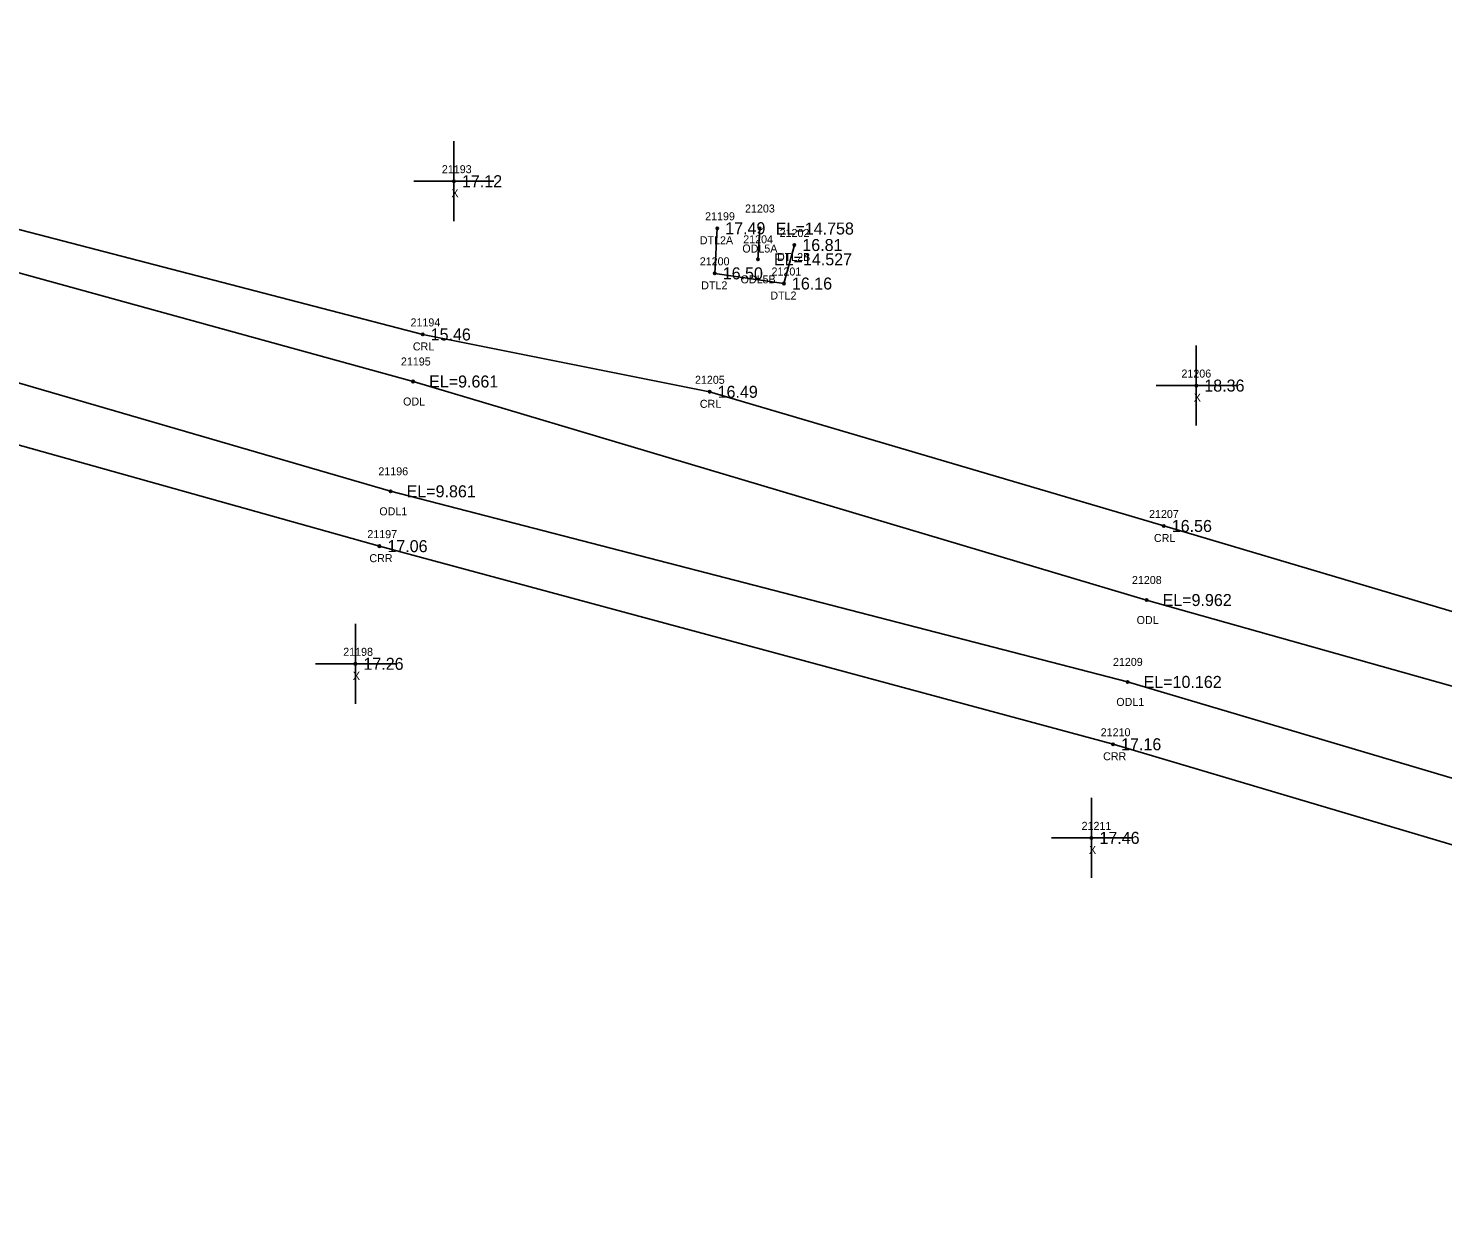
# Model space of a CAD drawing. Extents: x 2655177 to 2656219, y 761780 to 764748.
# Drawn here: x 2655865.5 to 2656042.3, y 763101.9 to 763251.6 of the extents above; entities that cross this region are included whole.
import ezdxf

# ---------------------------------------------------------------- set-up
doc = ezdxf.new("R2010")
doc.units = 0
for name, color, linetype in [('RD_EX_H2O', 7, 'Continuous'), ('RD_EX_H2O_txCode', 7, 'Continuous'), ('RD_EX_Misc', 7, 'Continuous'), ('RD_EX_Misc_txCode', 7, 'Continuous'), ('RD_EX_TX_H2O_ELEV', 7, 'Continuous'), ('RD_EX_TX_Misc_ELEV', 7, 'Continuous'), ('RD_SMD_Locator', 7, 'Continuous')]:
    doc.layers.add(name, color=color, linetype=linetype)

msp = doc.modelspace()

# ---------------------------------------------------------------- linework, layer by layer
at = {"layer": 'RD_EX_H2O'}
msp.add_line((2655956.93, 763226.61), (2655956.7, 763222.76), dxfattribs=at)
for points in [[(2655763.83, 763255.61), (2655817.49, 763238.63), (2655914.8, 763213.38), (2655950.66, 763206.21), (2656007.42, 763189.45), (2656109.25, 763159.23), (2656208.33, 763130.47)], [(2655756.39, 763249.8), (2655816.19, 763234.32), (2655913.6, 763207.5), (2656005.27, 763180.2), (2656107.53, 763151.42), (2656206.07, 763121.76)], [(2655730.43, 763238.59), (2655771.44, 763229.13), (2655791.17, 763220.85), (2655791.17, 763220.85), (2655810.24, 763214.7), (2655909.39, 763186.93), (2656001.09, 763162.18), (2656103.26, 763131.88), (2656200.94, 763101.91)], [(2655752.5, 763238.32), (2655812.56, 763222.36), (2655910.79, 763193.78), (2656002.9, 763169.97), (2656104.97, 763139.7), (2656202.94, 763109.66)], [(2655951.61, 763226.64), (2655951.3, 763221.01), (2655959.95, 763219.74), (2655961.25, 763224.55)]]:
    msp.add_lwpolyline(points, dxfattribs=at)
at = {"layer": 'RD_EX_Misc'}
for p, q in [((2655918.71, 763227.52), (2655918.71, 763237.52)), ((2655913.71, 763232.52), (2655923.71, 763232.52)), ((2656011.49, 763201.99), (2656011.49, 763211.99)), ((2656006.49, 763206.99), (2656016.49, 763206.99)), ((2655906.39, 763167.23), (2655906.39, 763177.23)), ((2655901.39, 763172.23), (2655911.39, 763172.23)), ((2655998.38, 763145.49), (2655998.38, 763155.49)), ((2655993.38, 763150.49), (2656003.38, 763150.49))]:
    msp.add_line(p, q, dxfattribs=at)
at = {"layer": 'RD_SMD_Locator'}
for centre in [(2655918.71, 763232.52), (2655951.61, 763226.64), (2655956.93, 763226.61), (2655961.25, 763224.55), (2655956.7, 763222.76), (2655951.3, 763221.01), (2655959.95, 763219.74), (2655914.8, 763213.38), (2655913.6, 763207.5), (2656011.49, 763206.99), (2655950.66, 763206.21), (2655910.79, 763193.78), (2656007.42, 763189.45), (2655909.39, 763186.93), (2656005.27, 763180.2), (2655906.39, 763172.23), (2656002.9, 763169.97), (2656001.09, 763162.18), (2655998.38, 763150.49)]:
    msp.add_circle(centre, 0.15, dxfattribs=at)

# ---------------------------------------------------------------- texts
at = {"layer": 'RD_EX_H2O_txCode'}
for s, p in [('21199', (2655950.1, 763227.64)), ('21203', (2655955.09, 763228.61)), ('21202', (2655959.41, 763225.55)), ('DTL2A', (2655949.43, 763224.64)), ('ODL5A', (2655954.75, 763223.61)), ('21204', (2655954.86, 763224.76)), ('21200', (2655949.43, 763222.01)), ('DTL2B', (2655959.08, 763222.55)), ('21201', (2655958.4, 763220.74)), ('DTL2', (2655949.61, 763219.01)), ('ODL5B', (2655954.53, 763219.76)), ('DTL2', (2655958.25, 763217.74)), ('21194', (2655913.28, 763214.38)), ('CRL', (2655913.57, 763211.38)), ('21195', (2655912.08, 763209.5)), ('21205', (2655948.83, 763207.21)), ('ODL', (2655912.35, 763204.5)), ('CRL', (2655949.44, 763204.21)), ('21196', (2655909.26, 763195.78)), ('ODL1', (2655909.38, 763190.78)), ('21207', (2656005.58, 763190.45)), ('21197', (2655907.88, 763187.93)), ('CRL', (2656006.19, 763187.45)), ('CRR', (2655908.14, 763184.93)), ('21208', (2656003.44, 763182.2)), ('ODL', (2656004.03, 763177.2)), ('21209', (2656001.07, 763171.97)), ('ODL1', (2656001.49, 763166.97)), ('21210', (2655999.54, 763163.18)), ('CRR', (2655999.84, 763160.18))]:
    msp.add_text(s, height=1, dxfattribs=at).set_placement(p)
at = {"layer": 'RD_EX_Misc_txCode'}
for s, p in [('21193', (2655917.2, 763233.52)), ('X', (2655918.39, 763230.52)), ('21206', (2656009.63, 763207.99)), ('X', (2656011.17, 763204.99)), ('21198', (2655904.87, 763173.23)), ('X', (2655906.07, 763170.23)), ('21211', (2655997.15, 763151.49)), ('X', (2655998.07, 763148.49))]:
    msp.add_text(s, height=1, dxfattribs=at).set_placement(p)
at = {"layer": 'RD_EX_TX_H2O_ELEV'}
for s, p in [('17.49', (2655952.61, 763225.89)), ('EL=14.758', (2655958.93, 763225.86)), ('16.81', (2655962.25, 763223.8)), ('EL=14.527', (2655958.7, 763222.01)), ('16.50', (2655952.3, 763220.26)), ('16.16', (2655960.95, 763218.99)), ('15.46', (2655915.8, 763212.63)), ('EL=9.661', (2655915.6, 763206.75)), ('16.49', (2655951.66, 763205.46)), ('EL=9.861', (2655912.79, 763193.03)), ('16.56', (2656008.42, 763188.7)), ('17.06', (2655910.39, 763186.18)), ('EL=9.962', (2656007.27, 763179.45)), ('EL=10.162', (2656004.9, 763169.22)), ('17.16', (2656002.09, 763161.43))]:
    msp.add_text(s, height=1.5, dxfattribs=at).set_placement(p)
at = {"layer": 'RD_EX_TX_Misc_ELEV'}
for s, p in [('17.12', (2655919.71, 763231.77)), ('18.36', (2656012.49, 763206.24)), ('17.26', (2655907.39, 763171.48)), ('17.46', (2655999.38, 763149.74))]:
    msp.add_text(s, height=1.5, dxfattribs=at).set_placement(p)

doc.saveas('drawing.dxf')
